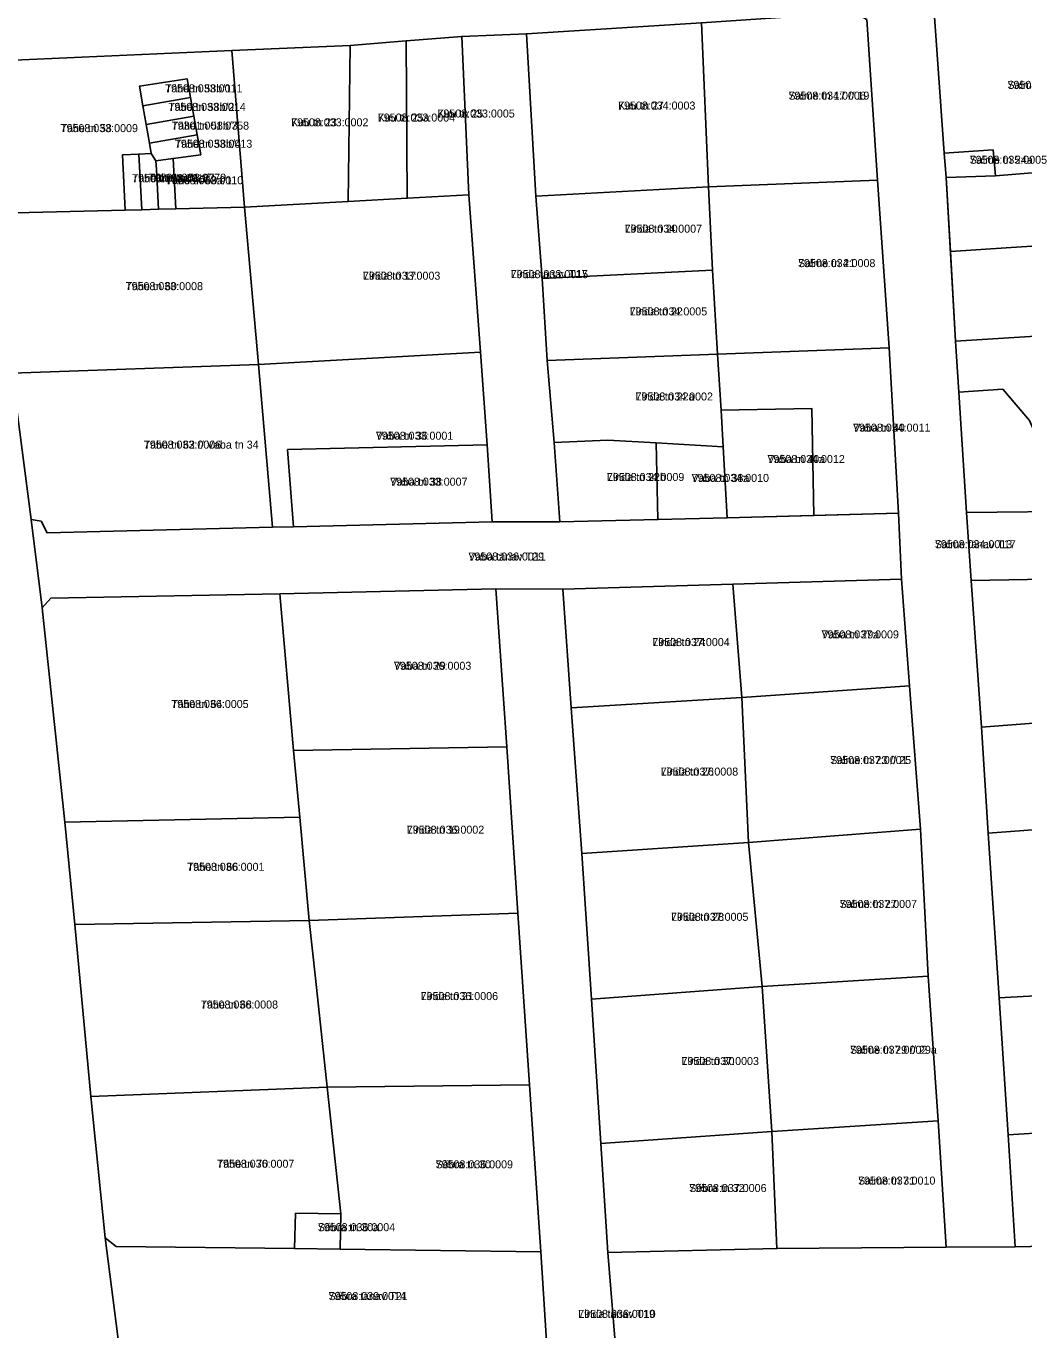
# Model space of a CAD drawing. Extents: x 643847 to 663718, y 6468443 to 6482775.
# Drawn here: x 659734 to 659921, y 6472589.6 to 6472833.9 of the extents above; entities that cross this region are included whole.
import ezdxf

# ---------------------------------------------------------------- set-up
doc = ezdxf.new("R2010")
doc.units = 0
for name, color, linetype in [('L_AADRESS', 7, 'Continuous'), ('PIIR', 7, 'Continuous'), ('TUNNUS', 7, 'Continuous')]:
    doc.layers.add(name, color=color, linetype=linetype)

msp = doc.modelspace()

# ---------------------------------------------------------------- linework, layer by layer
at = {"layer": 'PIIR'}
for points in [[(659720, 6472839.17), (659721.91, 6472827.14), (659726.79, 6472798.78), (659731.38, 6472768.86), (659734.92, 6472741.45), (659737.02, 6472724.87), (659741.28, 6472684.74), (659743.11, 6472665.55), (659746.14, 6472633.34), (659748.79, 6472606.82), (659751.78, 6472583.97)], [(659860.6, 6472834.56), (659827.78, 6472832.5), (659815.67, 6472832), (659805.22, 6472831.15), (659794.76, 6472830.3), (659772.57, 6472829.34), (659721.91, 6472827.14), (659720, 6472839.17)]]:
    msp.add_lwpolyline(points, dxfattribs=at)
for points in [[(659904.14, 6472837.44), (659929.28, 6472839.05), (659931.75, 6472807.15), (659915.69, 6472805.84), (659915.26, 6472810.72), (659906.1, 6472810.12)], [(659893.59, 6472805.05), (659861.89, 6472803.83), (659860.6, 6472834.56), (659889.28, 6472836.46), (659891.59, 6472835.14)], [(659889.28, 6472836.46), (659904.14, 6472837.44), (659906.1, 6472810.12), (659906.45, 6472805.55), (659908.23, 6472774.88), (659908.85, 6472765.34), (659910.3, 6472742.78), (659911.12, 6472730.04), (659913.07, 6472702.56), (659914.34, 6472682.67), (659916.39, 6472651.82), (659918.08, 6472626.11), (659919.39, 6472605.15), (659906.44, 6472605.05), (659904.93, 6472628.78), (659903.07, 6472655.87), (659901.66, 6472683.39), (659899.61, 6472710.29), (659898.09, 6472730.27), (659897.52, 6472742.66), (659895.8, 6472773.64), (659893.59, 6472805.05), (659891.59, 6472835.14)], [(659860.6, 6472834.56), (659861.89, 6472803.83), (659829.56, 6472802.03), (659827.78, 6472832.5)], [(659815.67, 6472832), (659816.96, 6472802.29), (659805.44, 6472801.66), (659805.22, 6472831.15)], [(659816.96, 6472802.29), (659815.67, 6472832), (659827.78, 6472832.5), (659829.56, 6472802.03), (659830.72, 6472786.6), (659831.69, 6472771.23), (659832.96, 6472755.86), (659834.03, 6472741), (659821.38, 6472741.01), (659820.43, 6472755.48), (659819.15, 6472772.81)], [(659721.91, 6472827.14), (659772.57, 6472829.34), (659774.91, 6472800.01), (659762.05, 6472799.68), (659761.55, 6472809.13), (659766.74, 6472809.83), (659766.07, 6472813.57), (659765.45, 6472817.08), (659764.82, 6472820.58), (659764.2, 6472824.02), (659755.24, 6472822.65), (659755.88, 6472819), (659756.51, 6472815.5), (659757.12, 6472811.99), (659757.47, 6472810.03), (659755.13, 6472809.93), (659752.05, 6472809.8), (659752.6, 6472799.44), (659726.79, 6472798.78)], [(659794.76, 6472830.3), (659794.38, 6472801.07), (659774.91, 6472800.01), (659772.57, 6472829.34)], [(659805.22, 6472831.15), (659805.44, 6472801.66), (659794.38, 6472801.07), (659794.76, 6472830.3)], [(659755.88, 6472819), (659755.24, 6472822.65), (659764.2, 6472824.02), (659764.82, 6472820.58)], [(659756.51, 6472815.5), (659755.88, 6472819), (659764.82, 6472820.58), (659765.45, 6472817.08)], [(659766.07, 6472813.57), (659757.12, 6472811.99), (659756.51, 6472815.5), (659765.45, 6472817.08)], [(659757.12, 6472811.99), (659766.07, 6472813.57), (659766.74, 6472809.83), (659761.55, 6472809.13), (659758.33, 6472808.69), (659757.47, 6472810.03)], [(659752.05, 6472809.8), (659755.13, 6472809.93), (659755.68, 6472799.52), (659752.6, 6472799.44)], [(659758.82, 6472799.6), (659755.68, 6472799.52), (659755.13, 6472809.93), (659757.47, 6472810.03), (659758.33, 6472808.69), (659758.42, 6472807.07)], [(659906.1, 6472810.12), (659915.26, 6472810.72), (659915.69, 6472805.84), (659906.45, 6472805.55)], [(659758.33, 6472808.69), (659761.55, 6472809.13), (659762.05, 6472799.68), (659758.82, 6472799.6), (659758.42, 6472807.07)], [(659907.25, 6472791.7), (659906.45, 6472805.55), (659915.69, 6472805.84), (659931.75, 6472807.15), (659944.66, 6472808.45), (659945.66, 6472794.17), (659917.7, 6472792.37)], [(659861.89, 6472803.83), (659893.59, 6472805.05), (659895.8, 6472773.64), (659863.59, 6472772.47), (659862.68, 6472788.2)], [(659819.15, 6472772.81), (659777.57, 6472770.5), (659774.91, 6472800.01), (659794.38, 6472801.07), (659805.44, 6472801.66), (659816.96, 6472802.29)], [(659829.56, 6472802.03), (659861.89, 6472803.83), (659862.68, 6472788.2), (659830.72, 6472786.6)], [(659726.79, 6472798.78), (659752.6, 6472799.44), (659755.68, 6472799.52), (659758.82, 6472799.6), (659762.05, 6472799.68), (659774.91, 6472800.01), (659777.57, 6472770.5), (659731.38, 6472768.86)], [(659908.23, 6472774.88), (659907.25, 6472791.7), (659917.7, 6472792.37), (659945.66, 6472794.17), (659946.85, 6472777.16), (659933.99, 6472776.51), (659925.2, 6472775.96)], [(659830.72, 6472786.6), (659862.68, 6472788.2), (659863.59, 6472772.47), (659831.69, 6472771.23)], [(659908.23, 6472774.88), (659925.2, 6472775.96), (659933.99, 6472776.51), (659936.39, 6472743.16), (659933.18, 6472743.02), (659932.08, 6472758.31), (659923.13, 6472757.59), (659922.1, 6472760), (659917.08, 6472765.87), (659908.85, 6472765.34)], [(659863.59, 6472772.47), (659895.8, 6472773.64), (659897.52, 6472742.66), (659881.63, 6472742.2), (659881.27, 6472762.28), (659864.29, 6472761.95)], [(659737.93, 6472738.98), (659736.81, 6472741.16), (659734.92, 6472741.45), (659731.38, 6472768.86), (659777.57, 6472770.5), (659780.17, 6472740.02)], [(659780.17, 6472740.02), (659777.57, 6472770.5), (659819.15, 6472772.81), (659820.43, 6472755.48), (659783, 6472754.57), (659784.15, 6472740.1)], [(659863.59, 6472772.47), (659864.29, 6472761.95), (659864.64, 6472755.05), (659852.08, 6472755.8), (659843.05, 6472756.34), (659832.96, 6472755.86), (659831.69, 6472771.23)], [(659933.18, 6472743.02), (659910.3, 6472742.78), (659908.85, 6472765.34), (659917.08, 6472765.87), (659922.1, 6472760), (659923.13, 6472757.59), (659932.08, 6472758.31)], [(659864.29, 6472761.95), (659881.27, 6472762.28), (659881.63, 6472742.2), (659865.43, 6472741.77), (659864.64, 6472755.05)], [(659834.03, 6472741), (659832.96, 6472755.86), (659843.05, 6472756.34), (659852.08, 6472755.8), (659852.43, 6472741.45)], [(659865.43, 6472741.77), (659852.43, 6472741.45), (659852.08, 6472755.8), (659864.64, 6472755.05)], [(659784.15, 6472740.1), (659783, 6472754.57), (659820.43, 6472755.48), (659821.38, 6472741.01)], [(659911.12, 6472730.04), (659910.3, 6472742.78), (659933.18, 6472743.02), (659936.39, 6472743.16), (659962.56, 6472743.53), (659987.66, 6472744.39), (659988.93, 6472731.66), (659949.97, 6472730.68)], [(659781.58, 6472727.52), (659738.64, 6472726.73), (659737.02, 6472724.87), (659734.92, 6472741.45), (659736.81, 6472741.16), (659737.93, 6472738.98), (659780.17, 6472740.02), (659784.15, 6472740.1), (659821.38, 6472741.01), (659834.03, 6472741), (659852.43, 6472741.45), (659865.43, 6472741.77), (659897.52, 6472742.66), (659898.09, 6472730.27), (659866.46, 6472729.32), (659834.61, 6472728.37), (659822.03, 6472728.45)], [(659834.61, 6472728.37), (659866.46, 6472729.32), (659868.15, 6472708.08), (659836.2, 6472706.13)], [(659898.09, 6472730.27), (659899.61, 6472710.29), (659868.15, 6472708.08), (659866.46, 6472729.32)], [(659949.97, 6472730.68), (659952.05, 6472705.52), (659913.07, 6472702.56), (659911.12, 6472730.04)], [(659737.02, 6472724.87), (659738.64, 6472726.73), (659781.58, 6472727.52), (659784.1, 6472698.13), (659785.28, 6472685.66), (659741.28, 6472684.74)], [(659822.03, 6472728.45), (659824.11, 6472698.87), (659784.1, 6472698.13), (659781.58, 6472727.52)], [(659824.11, 6472698.87), (659822.03, 6472728.45), (659834.61, 6472728.37), (659836.2, 6472706.13), (659838.16, 6472678.84), (659839.98, 6472651.54), (659841.75, 6472624.52), (659843.03, 6472604.06), (659844.75, 6472583.46), (659846.32, 6472556.05), (659847.93, 6472531.86), (659849.72, 6472505.07), (659851.13, 6472484), (659852.98, 6472459.26), (659839.95, 6472459.81), (659837.97, 6472487.82), (659835.88, 6472523.11), (659834.52, 6472543.3), (659831.8, 6472583.5), (659830.5, 6472604.22), (659828.36, 6472635.49), (659826.16, 6472667.68)], [(659901.66, 6472683.39), (659869.4, 6472680.94), (659868.15, 6472708.08), (659899.61, 6472710.29)], [(659836.2, 6472706.13), (659868.15, 6472708.08), (659869.4, 6472680.94), (659838.16, 6472678.84)], [(659913.07, 6472702.56), (659952.05, 6472705.52), (659953.63, 6472685.58), (659914.34, 6472682.67)], [(659826.16, 6472667.68), (659787.07, 6472666.27), (659785.28, 6472685.66), (659784.1, 6472698.13), (659824.11, 6472698.87)], [(659741.28, 6472684.74), (659785.28, 6472685.66), (659787.07, 6472666.27), (659743.11, 6472665.55)], [(659914.34, 6472682.67), (659953.63, 6472685.58), (659954.02, 6472680.47), (659955.99, 6472654.65), (659956.03, 6472654.01), (659916.39, 6472651.82)], [(659903.07, 6472655.87), (659871.94, 6472653.9), (659869.4, 6472680.94), (659901.66, 6472683.39)], [(659869.4, 6472680.94), (659871.94, 6472653.9), (659839.98, 6472651.54), (659838.16, 6472678.84)], [(659746.14, 6472633.34), (659743.11, 6472665.55), (659787.07, 6472666.27), (659788.23, 6472655.48), (659790.44, 6472635.07)], [(659828.36, 6472635.49), (659790.44, 6472635.07), (659788.23, 6472655.48), (659787.07, 6472666.27), (659826.16, 6472667.68)], [(659904.93, 6472628.78), (659873.76, 6472626.76), (659871.94, 6472653.9), (659903.07, 6472655.87)], [(659839.98, 6472651.54), (659871.94, 6472653.9), (659873.76, 6472626.76), (659841.75, 6472624.52)], [(659916.39, 6472651.82), (659956.03, 6472654.01), (659958.34, 6472628.73), (659944.16, 6472627.74), (659918.08, 6472626.11)], [(659750.9, 6472605.2), (659748.79, 6472606.82), (659746.14, 6472633.34), (659790.44, 6472635.07), (659793.01, 6472611.29), (659784.5, 6472611.44), (659784.34, 6472604.84)], [(659830.5, 6472604.22), (659792.86, 6472604.7), (659793.01, 6472611.29), (659790.44, 6472635.07), (659828.36, 6472635.49)], [(659906.44, 6472605.05), (659874.72, 6472604.82), (659873.76, 6472626.76), (659904.93, 6472628.78)], [(659841.75, 6472624.52), (659873.76, 6472626.76), (659874.72, 6472604.82), (659843.03, 6472604.06)], [(659919.39, 6472605.15), (659918.08, 6472626.11), (659944.16, 6472627.74), (659945.04, 6472605.68)], [(659784.34, 6472604.84), (659784.5, 6472611.44), (659793.01, 6472611.29), (659792.86, 6472604.7)], [(659795.26, 6472583.6), (659751.78, 6472583.97), (659748.79, 6472606.82), (659750.9, 6472605.2), (659784.34, 6472604.84), (659792.86, 6472604.7), (659830.5, 6472604.22), (659831.8, 6472583.5)], [(659876.89, 6472583.38), (659844.75, 6472583.46), (659843.03, 6472604.06), (659874.72, 6472604.82), (659906.44, 6472605.05), (659919.39, 6472605.15), (659945.04, 6472605.68), (659973.07, 6472606.17), (659986.28, 6472606.35), (659999.43, 6472606.53), (660001.06, 6472584), (659999.66, 6472585.31), (659998.34, 6472585.83), (659975.93, 6472585), (659945.57, 6472584.07), (659937.8, 6472584.46), (659929.15, 6472584.26), (659920.54, 6472584.03), (659907.78, 6472583.92)]]:
    msp.add_lwpolyline(points, close=True, dxfattribs=at)

# ---------------------------------------------------------------- texts
at = {"layer": 'L_AADRESS'}
for s, p in [('Tähe tn 58b/1', (659760.05, 6472821.51)), ('Salme tn 24', (659917.95, 6472822.17)), ('Tähe tn 58b/2', (659760.67, 6472818.04)), ('Kuu tn 27', (659844.95, 6472818.29)), ('Salme tn 17 // 19', (659876.9, 6472820.15)), ('Kuu tn 25a', (659799.91, 6472816.04)), ('Kuu tn 25', (659811.09, 6472816.8)), ('Tähe tn 58', (659740.46, 6472814.06)), ('Tähe tn 58b/3', (659761.29, 6472814.53)), ('Kuu tn 23', (659783.66, 6472815.15)), ('Tähe tn 58b/4', (659761.89, 6472811.13)), ('Salme tn 24a', (659910.87, 6472808.13)), ('Tähe tn 58a/3', (659753.86, 6472804.67)), ('Tähe tn 58a/2', (659756.98, 6472804.78)), ('Tähe tn 58a/1', (659760.19, 6472804.29)), ('Linda tn 20', (659846.2, 6472795.21)), ('Salme tn 21', (659878.69, 6472788.76)), ('Linda tn 17', (659797.14, 6472786.4)), ('Linda tänav T17', (659824.85, 6472786.69)), ('Tähe tn 60', (659752.65, 6472784.44)), ('Linda tn 22', (659847.16, 6472779.71)), ('Linda tn 22a', (659848.24, 6472763.76)), ('Vaba tn 40', (659889.01, 6472757.92)), ('Tähe tn 62 // Vaba tn 34', (659756.06, 6472754.74)), ('Vaba tn 36', (659799.57, 6472756.41)), ('Vaba tn 40a', (659872.96, 6472752.04)), ('Vaba tn 38', (659802.24, 6472747.79)), ('Linda tn 22b', (659842.87, 6472748.67)), ('Vaba tn 38a', (659858.75, 6472748.5)), ('Salme tänav T17', (659904.34, 6472736.08)), ('Vaba tänav T29', (659816.91, 6472733.77)), ('Linda tn 24', (659851.38, 6472717.73)), ('Vaba tn 29a', (659883.1, 6472719.17)), ('Vaba tn 29', (659802.95, 6472713.29)), ('Tähe tn 64', (659761.21, 6472706.13)), ('Salme tn 23 // 25', (659884.73, 6472695.62)), ('Linda tn 26', (659852.97, 6472693.46)), ('Linda tn 19', (659805.37, 6472682.57)), ('Tähe tn 66', (659764.18, 6472675.61)), ('Linda tn 28', (659854.89, 6472666.24)), ('Salme tn 27', (659886.49, 6472668.65)), ('Tähe tn 68', (659766.72, 6472649.8)), ('Linda tn 21', (659807.97, 6472651.38)), ('Salme tn 29 // 29a', (659888.43, 6472641.32)), ('Linda tn 30', (659856.86, 6472639.21)), ('Tähe tn 70', (659769.78, 6472619.96)), ('Sõbra tn 30', (659810.76, 6472619.85)), ('Sõbra tn 32', (659858.29, 6472615.41)), ('Salme tn 31', (659889.94, 6472616.8)), ('Sõbra tn 30a', (659788.68, 6472608.07)), ('Sõbra tänav T21', (659790.69, 6472595.16)), ('Linda tänav T19', (659837.5, 6472591.82))]:
    msp.add_text(s, height=1.5, dxfattribs=at).set_placement(p)
at = {"layer": 'TUNNUS'}
for s, p in [('79508:033:0011', (659760.05, 6472821.51)), ('79508:035:0010', (659917.95, 6472822.17)), ('79508:033:0014', (659760.67, 6472818.04)), ('79508:034:0003', (659844.95, 6472818.29)), ('79508:034:0006', (659876.9, 6472820.15)), ('79508:033:0004', (659799.91, 6472816.04)), ('79508:033:0005', (659811.09, 6472816.8)), ('79508:033:0009', (659740.46, 6472814.06)), ('79301:001:0758', (659761.29, 6472814.53)), ('79508:033:0002', (659783.66, 6472815.15)), ('79508:033:0013', (659761.89, 6472811.13)), ('79508:035:0005', (659910.87, 6472808.13)), ('79508:033:0012', (659753.86, 6472804.67)), ('79301:001:0779', (659756.98, 6472804.78)), ('79508:033:0010', (659760.19, 6472804.29)), ('79508:034:0007', (659846.2, 6472795.21)), ('79508:034:0008', (659878.69, 6472788.76)), ('79508:033:0003', (659797.14, 6472786.4)), ('79508:033:0015', (659824.85, 6472786.69)), ('79508:033:0008', (659752.65, 6472784.44)), ('79508:034:0005', (659847.16, 6472779.71)), ('79508:034:0002', (659848.24, 6472763.76)), ('79508:034:0011', (659889.01, 6472757.92)), ('79508:033:0006', (659756.06, 6472754.74)), ('79508:033:0001', (659799.57, 6472756.41)), ('79508:034:0012', (659872.96, 6472752.04)), ('79508:033:0007', (659802.24, 6472747.79)), ('79508:034:0009', (659842.87, 6472748.67)), ('79508:034:0010', (659858.75, 6472748.5)), ('79508:034:0013', (659904.34, 6472736.08)), ('79508:036:0011', (659816.91, 6472733.77)), ('79508:037:0004', (659851.38, 6472717.73)), ('79508:037:0009', (659883.1, 6472719.17)), ('79508:036:0003', (659802.95, 6472713.29)), ('79508:036:0005', (659761.21, 6472706.13)), ('79508:037:0001', (659884.73, 6472695.62)), ('79508:037:0008', (659852.97, 6472693.46)), ('79508:036:0002', (659805.37, 6472682.57)), ('79508:036:0001', (659764.18, 6472675.61)), ('79508:037:0007', (659886.49, 6472668.65)), ('79508:037:0005', (659854.89, 6472666.24)), ('79508:036:0008', (659766.72, 6472649.8)), ('79508:036:0006', (659807.97, 6472651.38)), ('79508:037:0002', (659888.43, 6472641.32)), ('79508:037:0003', (659856.86, 6472639.21)), ('79508:036:0007', (659769.78, 6472619.96)), ('79508:036:0009', (659810.76, 6472619.85)), ('79508:037:0006', (659858.29, 6472615.41)), ('79508:037:0010', (659889.94, 6472616.8)), ('79508:036:0004', (659788.68, 6472608.07)), ('79508:039:0014', (659790.69, 6472595.16)), ('79508:036:0010', (659837.5, 6472591.82))]:
    msp.add_text(s, height=1.5, dxfattribs=at).set_placement(p)

doc.saveas('drawing.dxf')
